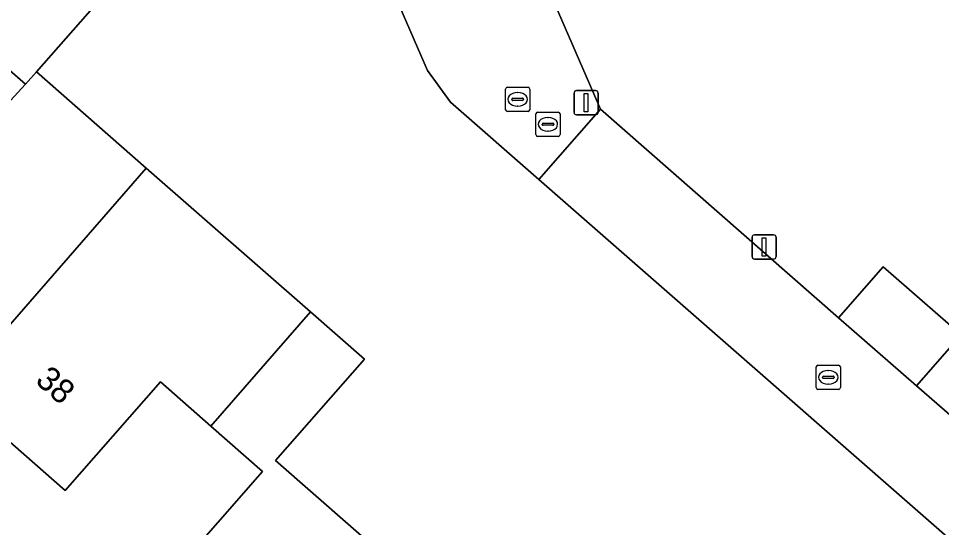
# Model space of a CAD drawing. Extents: x 158472 to 159562, y 388525 to 389606.
# Drawn here: x 158911.97 to 158950.04, y 388889.9 to 388910.91 of the extents above; entities that cross this region are included whole.
import ezdxf

# ---------------------------------------------------------------- set-up
doc = ezdxf.new("R2010")
doc.units = 0
for name, color, linetype in [('IMGEO_Erf', 7, 'Continuous'), ('IMGEO_Kolk', 7, 'Continuous'), ('IMGEO_Lichtmast', 7, 'Continuous'), ('IMGEO_Muur', 7, 'Continuous'), ('IMGEO_Pand', 7, 'Continuous'), ('IMGEO_Pand_nummerreeks', 7, 'Continuous'), ('IMGEO_Rijbaan_lokaal_open', 7, 'Continuous'), ('IMGEO_Rioolput', 7, 'Continuous'), ('IMGEO_Voetpad_open', 7, 'Continuous')]:
    doc.layers.add(name, color=color, linetype=linetype)

msp = doc.modelspace()

# ---------------------------------------------------------------- linework, layer by layer
at = {"layer": 'IMGEO_Erf'}
for points in [[(158916.349, 388912.847), (158912.713, 388908.701), (158917.24, 388904.733), (158921.825, 388900.714), (158924.012, 388898.797), (158926.241, 388896.842), (158922.576, 388892.663), (158927.12, 388888.678), (158929.463, 388886.623), (158930.515, 388887.823), (158932.528, 388887.999), (158933.736, 388886.94), (158935.906, 388885.038), (158940.415, 388881.084), (158938.432, 388878.823), (158940.675, 388876.856), (158943.023, 388874.797), (158945.014, 388877.068), (158946.766, 388875.531), (158955.225, 388885.178), (158933.436, 388904.261), (158929.786, 388907.457), (158928.836, 388908.759), (158918.298, 388933.043)], [(158928.728, 388923.855), (158935.982, 388907.162), (158945.799, 388898.553), (158947.637, 388900.659), (158950.849, 388897.857), (158953.895, 388895.199), (158952.057, 388893.093), (158953.206, 388892.096), (158955.047, 388894.211), (158958.302, 388891.378), (158956.461, 388889.263), (158960.457, 388885.716), (158982.198, 388910.573), (158963.265, 388927.1)], [(158910.711, 388906.512), (158912.265, 388908.19), (158907.959, 388911.966)], [(158900.523, 388899.222), (158914.066, 388887.291), (158912.414, 388885.487), (158939.514, 388861.675), (158945.42, 388868.506), (158943.295, 388870.369), (158939.343, 388865.862), (158934.659, 388869.969), (158930.044, 388874.016), (158933.984, 388878.509), (158931.833, 388880.395), (158929.729, 388882.24), (158925.793, 388877.751), (158921.132, 388881.838), (158916.502, 388885.897), (158922.039, 388892.211), (158919.91, 388894.078), (158917.823, 388895.908), (158913.895, 388891.428), (158909.218, 388895.529)]]:
    msp.add_lwpolyline(points, dxfattribs=at)
at = {"layer": 'IMGEO_Kolk'}
for p, q in [((158933.307, 388906.114), (158933.307, 388906.966)), ((158933.382, 388907.04), (158934.234, 388907.04)), ((158933.795, 388906.82), (158933.82, 388906.82)), ((158934.308, 388906.966), (158934.308, 388906.114)), ((158933.566, 388906.534), (158933.566, 388906.546)), ((158934.004, 388906.497), (158933.606, 388906.497)), ((158933.609, 388906.583), (158934.007, 388906.583)), ((158934.05, 388906.546), (158934.05, 388906.534)), ((158934.234, 388906.04), (158933.382, 388906.04)), ((158933.818, 388906.26), (158933.793, 388906.26)), ((158944.871, 388895.672), (158944.871, 388896.524)), ((158944.946, 388896.598), (158945.798, 388896.598)), ((158945.872, 388896.524), (158945.872, 388895.672)), ((158945.173, 388896.141), (158945.571, 388896.141)), ((158945.359, 388896.378), (158945.384, 388896.378)), ((158945.13, 388896.092), (158945.13, 388896.104)), ((158945.568, 388896.055), (158945.17, 388896.055)), ((158945.382, 388895.818), (158945.357, 388895.818)), ((158945.614, 388896.104), (158945.614, 388896.092)), ((158945.798, 388895.598), (158944.946, 388895.598))]:
    msp.add_line(p, q, dxfattribs=at)
for points in [[(158933.307, 388906.114), (158933.307, 388906.966)], [(158933.382, 388907.04), (158934.234, 388907.04)], [(158934.308, 388906.966), (158934.308, 388906.114)], [(158934.234, 388906.04), (158933.382, 388906.04)], [(158944.871, 388895.672), (158944.871, 388896.524)], [(158944.946, 388896.598), (158945.798, 388896.598)], [(158945.872, 388896.524), (158945.872, 388895.672)], [(158945.798, 388895.598), (158944.946, 388895.598)]]:
    msp.add_lwpolyline(points, dxfattribs=at)
for centre, radius, start, end in [((158933.384, 388906.964), 0.0765, 91.552, 178.448), ((158933.384, 388906.964), 0.0765, 91.552, 178.448), ((158934.232, 388906.964), 0.0765, 1.552, 88.448), ((158934.232, 388906.964), 0.0765, 1.552, 88.448), ((158933.606, 388906.543), 0.0403, 85.8775, 175.7526), ((158933.603, 388906.533), 0.0366, 178.938, 274.7102), ((158934.007, 388906.54), 0.043, 264.8664, 352.4533), ((158934.011, 388906.545), 0.0386, 1.7309, 96.639), ((158933.384, 388906.116), 0.0765, 181.552, 268.448), ((158933.384, 388906.116), 0.0765, 181.552, 268.448), ((158934.232, 388906.116), 0.0765, 271.552, 358.448), ((158934.232, 388906.116), 0.0765, 271.552, 358.448), ((158944.948, 388896.522), 0.0765, 91.552, 178.448), ((158944.948, 388896.522), 0.0765, 91.552, 178.448), ((158945.796, 388896.522), 0.0765, 1.552, 88.448), ((158945.796, 388896.522), 0.0765, 1.552, 88.448), ((158945.17, 388896.101), 0.0403, 85.8775, 175.7526), ((158945.575, 388896.103), 0.0386, 1.7309, 96.639), ((158945.167, 388896.091), 0.0366, 178.938, 274.7102), ((158945.571, 388896.098), 0.043, 264.8664, 352.4533), ((158944.948, 388895.674), 0.0765, 181.552, 268.448), ((158944.948, 388895.674), 0.0765, 181.552, 268.448), ((158945.796, 388895.674), 0.0765, 271.552, 358.448), ((158945.796, 388895.674), 0.0765, 271.552, 358.448)]:
    msp.add_arc(centre, radius, start, end, dxfattribs=at)
for centre, major_axis, ratio, start_param, end_param in [((158933.794, 388906.54), (-0.387, 0.002), 0.722429, 4.712389, 7.853982), ((158933.819, 388906.54), (-0.39, 0.002), 0.717154, 1.570796, 4.712389), ((158945.358, 388896.098), (-0.387, 0.002), 0.722429, 4.712389, 7.853982), ((158945.383, 388896.098), (-0.39, 0.002), 0.717154, 1.570796, 4.712389)]:
    msp.add_ellipse(centre, major_axis=major_axis, ratio=ratio, start_param=start_param, end_param=end_param, dxfattribs=at)
at = {"layer": 'IMGEO_Lichtmast'}
for p, q in [((158934.886, 388907.028), (158934.886, 388907.828)), ((158934.886, 388907.828), (158934.886, 388907.028)), ((158934.986, 388907.928), (158935.776, 388907.928)), ((158935.776, 388907.928), (158934.986, 388907.928)), ((158935.876, 388907.828), (158935.876, 388907.028)), ((158935.876, 388907.028), (158935.876, 388907.828)), ((158935.776, 388906.928), (158934.986, 388906.928)), ((158934.986, 388906.928), (158935.776, 388906.928)), ((158942.228, 388901.077), (158942.228, 388901.877)), ((158942.228, 388901.877), (158942.228, 388901.077)), ((158942.328, 388901.977), (158943.118, 388901.977)), ((158943.118, 388901.977), (158942.328, 388901.977)), ((158943.218, 388901.877), (158943.218, 388901.077)), ((158943.218, 388901.077), (158943.218, 388901.877)), ((158943.118, 388900.977), (158942.328, 388900.977)), ((158942.328, 388900.977), (158943.118, 388900.977))]:
    msp.add_line(p, q, dxfattribs=at)
for points in [[(158935.306, 388907.803), (158935.456, 388907.803), (158935.456, 388907.053), (158935.306, 388907.053), (158935.306, 388907.803)], [(158942.648, 388901.852), (158942.798, 388901.852), (158942.798, 388901.102), (158942.648, 388901.102), (158942.648, 388901.852)]]:
    msp.add_lwpolyline(points, dxfattribs=at)
for centre, start, end in [((158934.986, 388907.828), 90, 180), ((158934.986, 388907.828), 90, 180), ((158935.776, 388907.828), 0, 90), ((158935.776, 388907.828), 360, 90), ((158934.986, 388907.028), 180, 270), ((158934.986, 388907.028), 180, 270), ((158935.776, 388907.028), 270, 0), ((158935.776, 388907.028), 270, 0), ((158942.328, 388901.877), 90, 180), ((158942.328, 388901.877), 90, 180), ((158943.118, 388901.877), 0, 90), ((158943.118, 388901.877), 360, 90), ((158942.328, 388901.077), 180, 270), ((158942.328, 388901.077), 180, 270), ((158943.118, 388901.077), 270, 0), ((158943.118, 388901.077), 270, 0)]:
    msp.add_arc(centre, 0.1, start, end, dxfattribs=at)
at = {"layer": 'IMGEO_Muur'}
for points in [[(158933.436, 388904.261), (158929.786, 388907.457), (158928.836, 388908.759), (158918.298, 388933.043)], [(158955.225, 388885.178), (158933.436, 388904.261)]]:
    msp.add_lwpolyline(points, dxfattribs=at)
at = {"layer": 'IMGEO_Pand'}
for points in [[(158912.265, 388908.19), (158912.713, 388908.701), (158916.349, 388912.847), (158909.704, 388918.674), (158907.764, 388916.461), (158905.354, 388918.575), (158899.326, 388911.528), (158903.989, 388907.439), (158907.959, 388911.966)], [(158912.265, 388908.19), (158910.711, 388906.512), (158904.618, 388899.563), (158909.218, 388895.529), (158917.24, 388904.733), (158912.713, 388908.701)], [(158919.91, 388894.078), (158924.012, 388898.797), (158921.825, 388900.714), (158917.24, 388904.733), (158909.218, 388895.529), (158913.895, 388891.428), (158917.823, 388895.908)], [(158949.013, 388895.748), (158950.849, 388897.857), (158947.637, 388900.659), (158945.799, 388898.553)], [(158927.12, 388888.678), (158922.576, 388892.663), (158926.241, 388896.842), (158924.012, 388898.797), (158919.91, 388894.078), (158922.039, 388892.211), (158916.502, 388885.897), (158921.132, 388881.838)], [(158949.013, 388895.748), (158952.057, 388893.093), (158953.895, 388895.199), (158950.849, 388897.857)]]:
    msp.add_lwpolyline(points, close=True, dxfattribs=at)
at = {"layer": 'IMGEO_Rijbaan_lokaal_open'}
msp.add_lwpolyline([(158916.192, 388938.038), (158918.298, 388933.043), (158928.836, 388908.759), (158929.786, 388907.457), (158933.436, 388904.261), (158935.982, 388907.162), (158928.728, 388923.855), (158927.61, 388926.294), (158925.215, 388931.757)], dxfattribs=at)
at = {"layer": 'IMGEO_Rioolput'}
for p, q in [((158932.059, 388907.142), (158932.059, 388907.994)), ((158932.134, 388908.068), (158932.986, 388908.068)), ((158933.06, 388907.994), (158933.06, 388907.142)), ((158932.318, 388907.562), (158932.318, 388907.574)), ((158932.361, 388907.611), (158932.759, 388907.611)), ((158932.547, 388907.848), (158932.572, 388907.848)), ((158932.802, 388907.574), (158932.802, 388907.562)), ((158932.756, 388907.525), (158932.358, 388907.525)), ((158932.57, 388907.288), (158932.545, 388907.288)), ((158932.986, 388907.068), (158932.134, 388907.068))]:
    msp.add_line(p, q, dxfattribs=at)
for points in [[(158932.059, 388907.142), (158932.059, 388907.994)], [(158932.134, 388908.068), (158932.986, 388908.068)], [(158933.06, 388907.994), (158933.06, 388907.142)], [(158932.986, 388907.068), (158932.134, 388907.068)]]:
    msp.add_lwpolyline(points, dxfattribs=at)
for centre, radius, start, end in [((158932.136, 388907.992), 0.0765, 91.552, 178.448), ((158932.136, 388907.992), 0.0765, 91.552, 178.448), ((158932.984, 388907.992), 0.0765, 1.552, 88.448), ((158932.984, 388907.992), 0.0765, 1.552, 88.448), ((158932.358, 388907.571), 0.0403, 85.8775, 175.7526), ((158932.355, 388907.561), 0.0366, 178.938, 274.7102), ((158932.759, 388907.568), 0.043, 264.8664, 352.4533), ((158932.763, 388907.573), 0.0386, 1.7309, 96.639), ((158932.136, 388907.144), 0.0765, 181.552, 268.448), ((158932.136, 388907.144), 0.0765, 181.552, 268.448), ((158932.984, 388907.144), 0.0765, 271.552, 358.448), ((158932.984, 388907.144), 0.0765, 271.552, 358.448)]:
    msp.add_arc(centre, radius, start, end, dxfattribs=at)
for centre, major_axis, ratio, start_param, end_param in [((158932.546, 388907.568), (-0.387, 0.002), 0.722429, 4.712389, 7.853982), ((158932.571, 388907.568), (-0.39, 0.002), 0.717154, 1.570796, 4.712389)]:
    msp.add_ellipse(centre, major_axis=major_axis, ratio=ratio, start_param=start_param, end_param=end_param, dxfattribs=at)
at = {"layer": 'IMGEO_Voetpad_open'}
msp.add_lwpolyline([(158953.206, 388892.096), (158952.057, 388893.093), (158949.013, 388895.748), (158945.799, 388898.553), (158935.982, 388907.162), (158933.436, 388904.261), (158955.225, 388885.178), (158957.965, 388882.778), (158958.799, 388882.048), (158959.807, 388881.165), (158962.346, 388884.059), (158960.457, 388885.716), (158956.461, 388889.263)], close=True, dxfattribs=at)

# ---------------------------------------------------------------- texts
at = {"layer": 'IMGEO_Pand_nummerreeks'}
msp.add_text('38', height=1, rotation=318.7525, dxfattribs=at).set_placement((158912.619, 388895.9))

doc.saveas('drawing.dxf')
